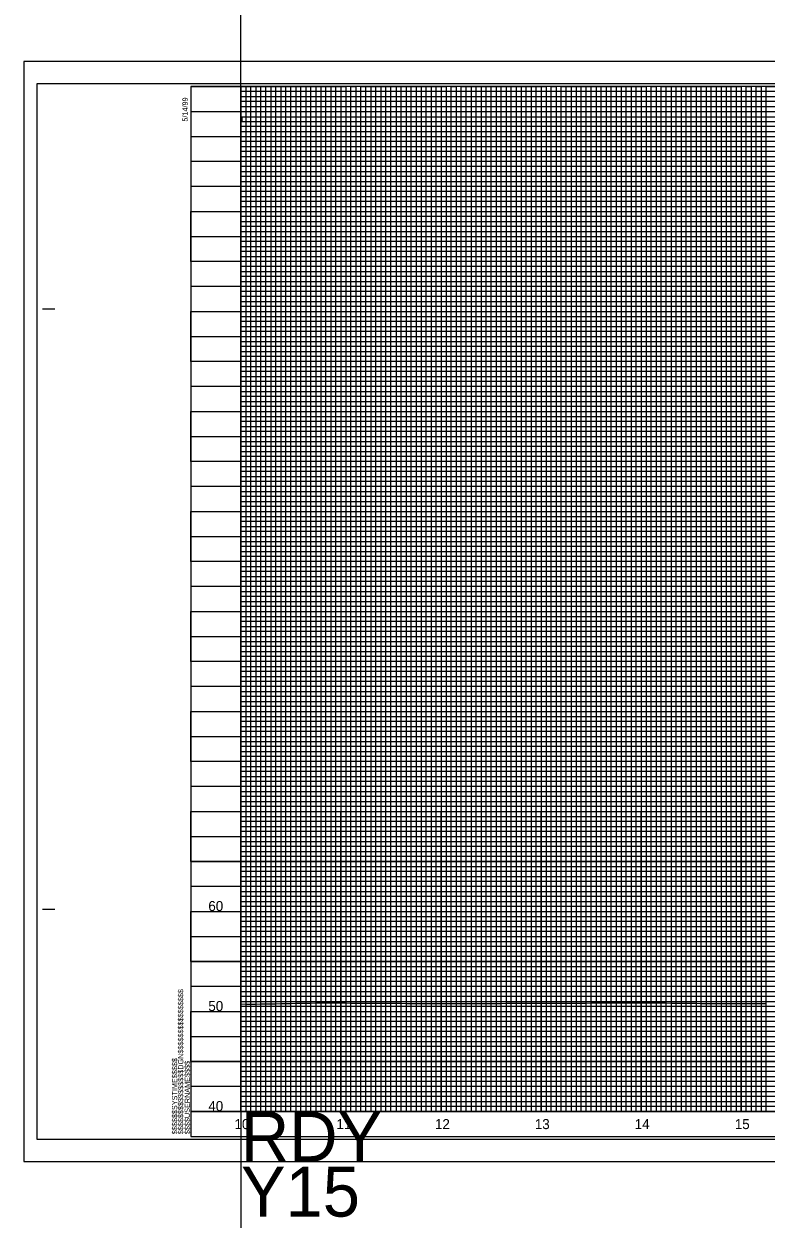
# Model space of a CAD drawing. Extents: x 2345490 to 2436403, y 465165 to 573888.
# Drawn here: x 2381550 to 2382292, y 523436 to 524631 of the extents above; entities that cross this region are included whole.
import ezdxf

# ---------------------------------------------------------------- set-up
doc = ezdxf.new("R2010")
doc.units = 0
for name, color, linetype in [('Old_Level_1', 7, 'Continuous'), ('Old_Level_18', 7, 'Continuous'), ('Old_Level_40', 7, 'Continuous'), ('Old_Level_41', 7, 'Continuous'), ('Old_Level_42', 7, 'Continuous'), ('Old_Level_43', 7, 'Continuous'), ('Old_Level_50', 7, 'Continuous'), ('Old_Level_51', 7, 'Continuous'), ('Old_Level_52', 7, 'Continuous'), ('Old_Level_57', 7, 'Continuous'), ('Old_Level_63', 7, 'Continuous')]:
    doc.layers.add(name, color=color, linetype=linetype)

msp = doc.modelspace()

# ---------------------------------------------------------------- linework, layer by layer
at = {"layer": 'Old_Level_1'}
for points in [[(2381766.799, 523650.76525), (2381771.799, 523650.5205), (2381776.799, 523650.612), (2381781.799, 523650.7035), (2381786.799, 523650.795), (2381791.799, 523650.8865), (2381796.799, 523650.978), (2381801.799, 523651.0665), (2381806.799, 523651.15825), (2381811.799, 523651.24975), (2381816.799, 523651.34125), (2381821.799, 523651.433), (2381826.799, 523651.5245), (2381831.799, 523651.6135), (2381836.799, 523651.70525), (2381841.799, 523651.797), (2381846.799, 523651.8885), (2381851.799, 523651.882), (2381856.799, 523651.84925), (2381861.799, 523651.81675), (2381866.799, 523651.784), (2381871.799, 523651.7515), (2381876.799, 523651.71875), (2381881.799, 523651.6925), (2381886.799, 523651.6605), (2381891.799, 523651.62825), (2381896.799, 523651.59625), (2381901.799, 523651.56425), (2381906.799, 523651.532), (2381911.799, 523651.51125), (2381916.799, 523651.47975), (2381921.799, 523651.44825), (2381926.799, 523651.417), (2381931.799, 523651.40325), (2381936.799, 523651.3975), (2381941.799, 523651.39175), (2381946.799, 523651.38575), (2381951.799, 523651.38), (2381956.799, 523651.37425), (2381961.799, 523651.371), (2381966.799, 523651.3645), (2381971.799, 523651.358), (2381976.799, 523651.3515), (2381981.799, 523651.34575), (2381986.799, 523651.3405), (2381991.799, 523651.336), (2381996.799, 523651.33125), (2382001.799, 523651.32625), (2382006.799, 523651.3215), (2382011.799, 523651.328), (2382016.799, 523651.3485), (2382021.799, 523651.369), (2382026.799, 523651.3895), (2382031.799, 523651.40975), (2382036.799, 523651.43025), (2382041.799, 523651.45075), (2382046.799, 523651.47125), (2382051.799, 523651.4915), (2382056.799, 523651.512), (2382061.799, 523651.5325), (2382066.799, 523651.553), (2382071.799, 523651.5735), (2382076.799, 523651.594), (2382081.799, 523651.61425), (2382086.799, 523651.63475), (2382091.799, 523651.6555), (2382096.799, 523651.677), (2382101.799, 523651.6985), (2382106.799, 523651.71925), (2382111.799, 523651.74025), (2382116.799, 523651.761), (2382121.799, 523651.78175), (2382126.799, 523651.8025), (2382131.799, 523651.82325), (2382136.799, 523651.84175), (2382141.799, 523651.86225), (2382146.799, 523651.88275), (2382151.799, 523651.90325), (2382156.799, 523651.92375), (2382161.799, 523651.9445), (2382166.799, 523651.965), (2382171.799, 523651.94075), (2382176.799, 523651.90025), (2382181.799, 523651.8575), (2382186.799, 523651.81275), (2382191.799, 523651.766), (2382196.799, 523651.717), (2382201.799, 523651.66625), (2382206.799, 523651.61325), (2382211.799, 523651.5585), (2382216.799, 523651.5015), (2382221.799, 523651.4425), (2382226.799, 523651.396), (2382231.799, 523651.35075), (2382236.799, 523651.28625), (2382241.799, 523651.21925), (2382246.799, 523651.187), (2382251.799, 523651.229), (2382256.799, 523651.25125), (2382261.799, 523651.271), (2382266.799, 523651.28825)], [(2382266.799, 523651.28825), (2382271.799, 523651.303), (2382276.799, 523651.315), (2382281.799, 523651.32475), (2382286.799, 523651.332), (2382291.799, 523651.3365)]]:
    msp.add_lwpolyline(points, dxfattribs=at)
at = {"layer": 'Old_Level_18'}
msp.add_line((2381716.79875, 523518.168), (2381716.79875, 523518.168), dxfattribs=at)
msp.add_line((2381716.79875, 523518.168), (2381716.79875, 523518.168), dxfattribs=at)
msp.add_lwpolyline([(2383216.79875, 524568.168), (2381716.79875, 524568.168), (2381716.79875, 523518.168), (2383216.79875, 523518.168)], close=True, dxfattribs=at)
at = {"layer": 'Old_Level_40'}
msp.add_line((2381716.79875, 523518.168), (2381716.79875, 523518.168), dxfattribs=at)
msp.add_line((2381716.79875, 523518.168), (2381716.79875, 523518.168), dxfattribs=at)
msp.add_line((2381716.79875, 523518.168), (2381716.79875, 523518.168), dxfattribs=at)
msp.add_line((2381716.79875, 523518.168), (2381716.79875, 523518.168), dxfattribs=at)
at = {"layer": 'Old_Level_41'}
for p, q in [((2381568.29875, 524345.668), (2381580.79875, 524345.668)), ((2381568.29875, 523745.668), (2381580.79875, 523745.668)), ((2383216.79875, 523543.168), (2381716.79875, 523543.168))]:
    msp.add_line(p, q, dxfattribs=at)
for points in [[(2381716.79875, 524568.168), (2381766.79875, 524568.168), (2381766.79875, 523543.168), (2381816.79875, 523543.168), (2381816.79875, 524568.168), (2381866.79875, 524568.168), (2381866.79875, 523543.168), (2381916.79875, 523543.168), (2381916.79875, 524568.168), (2381966.79875, 524568.168), (2381966.79875, 523543.168), (2382016.79875, 523543.168), (2382016.79875, 524568.168), (2382066.79875, 524568.168), (2382066.79875, 523543.168), (2382116.79875, 523543.168), (2382116.79875, 524568.168), (2382166.79875, 524568.168), (2382166.79875, 523543.168), (2382216.79875, 523543.168), (2382216.79875, 524568.168), (2382266.79875, 524568.168), (2382266.79875, 523543.168), (2382316.79875, 523543.168)], [(2381791.79875, 523543.168), (2381791.79875, 524568.168), (2381841.79875, 524568.168), (2381841.79875, 523543.168), (2381891.79875, 523543.168), (2381891.79875, 524568.168), (2381941.79875, 524568.168), (2381941.79875, 523543.168), (2381991.79875, 523543.168), (2381991.79875, 524568.168), (2382041.79875, 524568.168), (2382041.79875, 523543.168), (2382091.79875, 523543.168), (2382091.79875, 524568.168), (2382141.79875, 524568.168), (2382141.79875, 523543.168), (2382191.79875, 523543.168), (2382191.79875, 524568.168), (2382241.79875, 524568.168), (2382241.79875, 523543.168), (2382291.79875, 523543.168), (2382291.79875, 524568.168), (2382341.79875, 524568.168)], [(2381716.79875, 524518.168), (2383016.74875, 524518.168)], [(2383016.74875, 524468.168), (2381716.79875, 524468.168), (2381716.79875, 524418.118), (2383216.79875, 524418.118)], [(2383216.79875, 524393.168), (2381716.79875, 524393.168), (2381716.79875, 524443.168), (2383016.74875, 524443.168)], [(2383216.79875, 524368.168), (2381716.79875, 524368.168), (2381716.79875, 524318.168), (2383216.79875, 524318.168)], [(2383216.79875, 524293.168), (2381716.79875, 524293.168), (2381716.79875, 524343.168), (2383216.79875, 524343.168)], [(2383216.79875, 524268.168), (2381716.79875, 524268.168), (2381716.79875, 524218.168), (2383216.79875, 524218.168)], [(2383216.79875, 524168.168), (2381716.79875, 524168.168), (2381716.79875, 524118.168), (2383216.79875, 524118.168)], [(2383216.79875, 524068.168), (2381716.79875, 524068.168), (2381716.79875, 524018.168), (2383216.79875, 524018.168)], [(2383216.79875, 523968.168), (2381716.79875, 523968.168), (2381716.79875, 523918.168), (2383216.79875, 523918.168)], [(2383216.79875, 523893.168), (2381716.79875, 523893.168), (2381716.79875, 523943.168), (2383216.79875, 523943.168)], [(2383216.79875, 523868.168), (2381716.79875, 523868.168), (2381716.79875, 523818.168), (2383216.79875, 523818.168)], [(2383216.79875, 523793.168), (2381716.79875, 523793.168), (2381716.79875, 523843.168), (2383216.79875, 523843.168)], [(2383216.79875, 523768.168), (2381716.79875, 523768.168), (2381716.79875, 523718.168), (2383216.79875, 523718.168)], [(2383216.79875, 523668.168), (2381716.79875, 523668.168), (2381716.79875, 523618.168), (2383216.79875, 523618.168)], [(2383216.79875, 523593.168), (2381716.79875, 523593.168), (2381716.79875, 523643.168), (2383216.79875, 523643.168)], [(2383216.79875, 523568.168), (2381716.79875, 523568.168)], [(2381754.29875, 523518.168), (2381754.29875, 523518.168)]]:
    msp.add_lwpolyline(points, dxfattribs=at)
at = {"layer": 'Old_Level_42'}
for points in [[(2383016.74875, 524493.168), (2381716.89875, 524493.168), (2381716.89875, 524543.118), (2383016.74875, 524543.118)], [(2383216.79875, 524193.168), (2381716.79875, 524193.168), (2381716.79875, 524243.168), (2383216.79875, 524243.168)], [(2383216.79875, 524093.168), (2381716.79875, 524093.168), (2381716.79875, 524143.168), (2383216.79875, 524143.168)], [(2383216.79875, 523993.168), (2381716.79875, 523993.168), (2381716.79875, 524043.168), (2383216.79875, 524043.168)], [(2383216.79875, 523693.168), (2381716.79875, 523693.168), (2381716.79875, 523743.168), (2383216.79875, 523743.168)]]:
    msp.add_lwpolyline(points, dxfattribs=at)
at = {"layer": 'Old_Level_43'}
for p, q in [((2383166.79875, 524388.168), (2381766.79875, 524388.168)), ((2381766.79875, 524388.168), (2381766.79875, 524383.168)), ((2381766.79875, 524383.168), (2383166.79875, 524383.168)), ((2383166.79875, 524363.168), (2381766.79875, 524363.168))]:
    msp.add_line(p, q, dxfattribs=at)
for points in [[(2381771.79875, 524568.168), (2381776.79875, 524568.168), (2381781.79875, 524568.168), (2381786.79875, 524568.168), (2381796.79875, 524568.168), (2381763.74875, 524568.168), (2381768.74875, 524568.168), (2381726.79875, 524568.168), (2381731.79875, 524568.168), (2381736.79875, 524568.168), (2381746.79875, 524568.168), (2381751.79875, 524568.168), (2381756.79875, 524568.168), (2381761.79875, 524568.168), (2381771.79875, 524568.168), (2381771.79875, 523543.168), (2381776.79875, 523543.168), (2381776.79875, 524568.168), (2381781.79875, 524568.168), (2381781.79875, 523543.168), (2381786.79875, 523543.168), (2381786.79875, 524568.168), (2381796.79875, 524568.168), (2381796.79875, 523543.168), (2381801.79875, 523543.168), (2381801.79875, 524568.168), (2381806.79875, 524568.168), (2381806.79875, 523543.168), (2381811.79875, 523543.168), (2381811.79875, 524568.168), (2381821.79875, 524568.168), (2381821.79875, 523543.168), (2381826.79875, 523543.168), (2381826.79875, 524568.168), (2381831.79875, 524568.168), (2381831.79875, 523543.168), (2381836.79875, 523543.168), (2381836.79875, 524568.168), (2381846.79875, 524568.168), (2381846.79875, 523543.168), (2381851.79875, 523543.168), (2381851.79875, 524568.168), (2381856.79875, 524568.168), (2381856.79875, 523543.168), (2381861.79875, 523543.168), (2381861.79875, 524568.168), (2381871.79875, 524568.168), (2381871.79875, 523543.168), (2381876.79875, 523543.168), (2381876.79875, 524568.168), (2381881.79875, 524568.168), (2381881.79875, 523543.168), (2381886.79875, 523543.168), (2381886.79875, 524568.168), (2381896.79875, 524568.168), (2381896.79875, 523543.168), (2381901.79875, 523543.168), (2381901.79875, 524568.168), (2381906.79875, 524568.168), (2381906.79875, 523543.168), (2381911.79875, 523543.168), (2381911.79875, 524568.168), (2381921.79875, 524568.168), (2381921.79875, 523543.168), (2381926.79875, 523543.168), (2381926.79875, 524568.168), (2381931.79875, 524568.168), (2381931.79875, 523543.168)], [(2381931.79875, 523543.168), (2381936.79875, 523543.168), (2381936.79875, 524568.168), (2381946.79875, 524568.168), (2381946.79875, 523543.168), (2381951.79875, 523543.168), (2381951.79875, 524568.168), (2381956.79875, 524568.168), (2381956.79875, 523543.168), (2381961.79875, 523543.168), (2381961.79875, 524568.168), (2381971.79875, 524568.168), (2381971.79875, 523543.168), (2381976.79875, 523543.168), (2381976.79875, 524568.168), (2381976.79875, 524568.168), (2381981.79875, 524568.168), (2381981.79875, 523543.168), (2381986.79875, 523543.168), (2381986.79875, 524568.168), (2381996.79875, 524568.168), (2381996.79875, 523543.168), (2382001.79875, 523543.168), (2382001.79875, 524568.168), (2382006.79875, 524568.168), (2382006.79875, 523543.168), (2382011.79875, 523543.168), (2382011.79875, 524568.168), (2382021.79875, 524568.168), (2382021.79875, 523543.168), (2382026.79875, 523543.168), (2382026.79875, 524568.168), (2382031.79875, 524568.168), (2382031.79875, 523543.168), (2382036.79875, 523543.168), (2382036.79875, 524568.168), (2382046.79875, 524568.168), (2382046.79875, 523543.168), (2382051.79875, 523543.168), (2382051.79875, 524568.168), (2382056.79875, 524568.168), (2382056.79875, 523543.168), (2382061.79875, 523543.168), (2382061.79875, 524568.168), (2382071.79875, 524568.168), (2382071.79875, 523543.168), (2382076.79875, 523543.168), (2382076.79875, 524568.168), (2382081.79875, 524568.168), (2382081.79875, 523543.168), (2382086.79875, 523543.168), (2382086.79875, 524568.168), (2382096.79875, 524568.168), (2382096.79875, 523543.168), (2382111.79875, 523543.168), (2382111.79875, 524568.168), (2382121.79875, 524568.168), (2382121.79875, 523543.168), (2382126.79875, 523543.168), (2382126.79875, 524568.168), (2382131.79875, 524568.168), (2382131.79875, 523543.168), (2382136.79875, 523543.168), (2382136.79875, 524568.168), (2382146.79875, 524568.168), (2382146.79875, 523543.168), (2382151.79875, 523543.168), (2382151.79875, 524568.168), (2382156.79875, 524568.168), (2382156.79875, 523543.168), (2382161.79875, 523543.168), (2382161.79875, 524568.168), (2382171.79875, 524568.168), (2382171.79875, 523543.168), (2382176.79875, 523543.168), (2382176.79875, 524568.168), (2382181.79875, 524568.168), (2382181.79875, 523543.168), (2382186.79875, 523543.168), (2382186.79875, 524568.168), (2382196.79875, 524568.168), (2382196.79875, 523543.168), (2382201.79875, 523543.168), (2382201.79875, 524568.168), (2382206.79875, 524568.168), (2382206.79875, 523543.168), (2382211.79875, 523543.168), (2382211.79875, 524568.168), (2382221.79875, 524568.168), (2382221.79875, 523543.168), (2382226.79875, 523543.168), (2382226.79875, 524568.168), (2382231.79875, 524568.168), (2382231.79875, 523543.168), (2382236.79875, 523543.168), (2382236.79875, 524568.168), (2382246.79875, 524568.168), (2382246.79875, 523543.168)], [(2382101.79875, 524568.168), (2382101.79875, 523543.168), (2382106.79875, 523543.168), (2382106.79875, 524568.168)], [(2382101.79875, 524567.568), (2382101.79875, 523543.168), (2382106.79875, 523543.168), (2382106.79875, 524567.568)], [(2382251.79875, 524568.168), (2382251.79875, 523543.168), (2382256.79875, 523543.168), (2382256.79875, 524568.168), (2382261.79875, 524568.168), (2382261.79875, 523543.168), (2382271.79875, 523543.168), (2382271.79875, 524568.168), (2382276.79875, 524568.168), (2382276.79875, 523543.168), (2382281.79875, 523543.168), (2382281.79875, 524568.168), (2382286.79875, 524568.168), (2382286.79875, 523543.168)], [(2383016.74875, 524563.168), (2381766.79875, 524563.168), (2381766.79875, 524558.168), (2383016.74875, 524558.168)], [(2383016.74875, 524553.168), (2381766.79875, 524553.168), (2381766.79875, 524548.168), (2383016.74875, 524548.168)], [(2383016.74875, 524537.418), (2381767.79875, 524537.418), (2381767.79875, 524533.168), (2383016.74875, 524533.168)], [(2383016.74875, 524528.168), (2381766.79875, 524528.168), (2381766.79875, 524523.168), (2383016.74875, 524523.168)], [(2383016.74875, 524513.168), (2381766.79875, 524513.168), (2381766.79875, 524508.168), (2383016.74875, 524508.168)], [(2383016.74875, 524503.168), (2381766.79875, 524503.168), (2381766.79875, 524498.168), (2383016.74875, 524498.168)], [(2383016.74875, 524488.168), (2381766.79875, 524488.168), (2381766.79875, 524483.168), (2383016.74875, 524483.168)], [(2383016.74875, 524478.168), (2381766.79875, 524478.168), (2381766.79875, 524473.168), (2383016.74875, 524473.168)], [(2383016.74875, 524463.168), (2381766.79875, 524463.168), (2381766.79875, 524458.168), (2383016.74875, 524458.168)], [(2383016.74875, 524453.168), (2381766.79875, 524453.168), (2381766.79875, 524448.168), (2383016.74875, 524448.168)], [(2383016.74875, 524438.168), (2381766.79875, 524438.168), (2381766.79875, 524433.168), (2383016.74875, 524433.168)], [(2383166.79875, 524428.168), (2381766.79875, 524428.168), (2381766.79875, 524428.168), (2381766.79875, 524408.168), (2383166.79875, 524408.168)], [(2381766.79875, 524423.168), (2383166.79875, 524423.168)], [(2383166.79875, 524413.168), (2381766.79875, 524413.168)], [(2383166.79875, 524403.168), (2381766.79875, 524403.168), (2381766.79875, 524398.168), (2383166.79875, 524398.168)], [(2383166.79875, 524378.168), (2381766.79875, 524378.168), (2381766.79875, 524373.168), (2383166.79875, 524373.168)], [(2383166.79875, 524358.168), (2381766.79875, 524358.168), (2381766.79875, 524353.168), (2383166.79875, 524353.168)], [(2383166.79875, 524348.168), (2381766.79875, 524348.168)], [(2381766.79875, 524338.168), (2383166.79875, 524338.168)], [(2383166.79875, 524333.168), (2381766.79875, 524333.168), (2381766.79875, 524328.168), (2383166.79875, 524328.168)], [(2383166.79875, 524323.168), (2381766.79875, 524323.168), (2381766.79875, 524313.168), (2383166.79875, 524313.168)], [(2383166.79875, 524308.168), (2381766.79875, 524308.168), (2381766.79875, 524303.168), (2383166.79875, 524303.168)], [(2383166.79875, 524298.168), (2381766.79875, 524298.168), (2381766.79875, 524288.168), (2383166.79875, 524288.168)], [(2383166.79875, 524283.168), (2381766.79875, 524283.168), (2381766.79875, 524278.168), (2383166.79875, 524278.168)], [(2383166.79875, 524273.168), (2381766.79875, 524273.168), (2381766.79875, 524263.168), (2383166.79875, 524263.168)], [(2383166.79875, 524258.168), (2381766.79875, 524258.168), (2381766.79875, 524253.168), (2383166.79875, 524253.168)], [(2383166.79875, 524248.168), (2381766.79875, 524248.168), (2381766.79875, 524238.168), (2383166.79875, 524238.168)], [(2383166.79875, 524233.168), (2381766.79875, 524233.168), (2381766.79875, 524228.168), (2383166.79875, 524228.168)], [(2383166.79875, 524223.168), (2381766.79875, 524223.168), (2381766.79875, 524213.168), (2383166.79875, 524213.168)], [(2383166.79875, 524208.168), (2381766.79875, 524208.168), (2381766.79875, 524203.168), (2383166.79875, 524203.168)], [(2383166.79875, 524198.168), (2381766.79875, 524198.168), (2381766.79875, 524188.168), (2383166.79875, 524188.168)], [(2383166.79875, 524183.168), (2381766.79875, 524183.168), (2381766.79875, 524178.168), (2383166.79875, 524178.168)], [(2383166.79875, 524173.168), (2381766.79875, 524173.168), (2381766.79875, 524163.168), (2383166.79875, 524163.168)], [(2383166.79875, 524158.168), (2381766.79875, 524158.168), (2381766.79875, 524153.168), (2383166.79875, 524153.168)], [(2383166.79875, 524148.168), (2381766.79875, 524148.168), (2381766.79875, 524138.168), (2383166.79875, 524138.168)], [(2383166.79875, 524133.168), (2381766.79875, 524133.168), (2381766.79875, 524128.168), (2383166.79875, 524128.168)], [(2383166.79875, 524123.168), (2381766.79875, 524123.168), (2381766.79875, 524113.168), (2383166.79875, 524113.168)], [(2383166.79875, 524108.168), (2381766.79875, 524108.168), (2381766.79875, 524103.168), (2383166.79875, 524103.168)], [(2383166.79875, 524098.168), (2381766.79875, 524098.168), (2381766.79875, 524088.168), (2383166.79875, 524088.168)], [(2383166.79875, 524083.168), (2381766.79875, 524083.168), (2381766.79875, 524078.168), (2383166.79875, 524078.168)], [(2383166.79875, 524073.168), (2381766.79875, 524073.168), (2381766.79875, 524063.168), (2383166.79875, 524063.168)], [(2383166.79875, 524058.168), (2381766.79875, 524058.168), (2381766.79875, 524053.168), (2383166.79875, 524053.168)], [(2383166.79875, 524048.168), (2381766.79875, 524048.168)], [(2381766.79875, 524038.168), (2383166.79875, 524038.168)], [(2383166.79875, 524033.168), (2381766.79875, 524033.168), (2381766.79875, 524028.168), (2383166.79875, 524028.168)], [(2383166.79875, 524023.168), (2381766.79875, 524023.168), (2381766.79875, 524013.168), (2383166.79875, 524013.168)], [(2383166.79875, 524008.168), (2381766.79875, 524008.168), (2381766.79875, 524003.168), (2383166.79875, 524003.168)], [(2383166.79875, 523998.168), (2381766.79875, 523998.168), (2381766.79875, 523988.168), (2383166.79875, 523988.168)], [(2383166.79875, 523983.168), (2381766.79875, 523983.168), (2381766.79875, 523978.168), (2383166.79875, 523978.168)], [(2383166.79875, 523973.168), (2381766.79875, 523973.168), (2381766.79875, 523963.168), (2383166.79875, 523963.168)], [(2383166.79875, 523958.168), (2381766.79875, 523958.168), (2381766.79875, 523953.168), (2383166.79875, 523953.168)], [(2383166.79875, 523948.168), (2381766.79875, 523948.168), (2381766.79875, 523938.168), (2383166.79875, 523938.168)], [(2383166.79875, 523933.168), (2381766.79875, 523933.168), (2381766.79875, 523928.168), (2383166.79875, 523928.168)], [(2383166.79875, 523923.168), (2381766.79875, 523923.168), (2381766.79875, 523913.168), (2383166.79875, 523913.168)], [(2383166.79875, 523908.168), (2381766.79875, 523908.168), (2381766.79875, 523903.168), (2383166.79875, 523903.168)], [(2383166.79875, 523898.168), (2381766.79875, 523898.168), (2381766.79875, 523888.168), (2383166.79875, 523888.168)], [(2383166.79875, 523883.168), (2381766.79875, 523883.168), (2381766.79875, 523878.168), (2383166.79875, 523878.168)], [(2383166.79875, 523873.168), (2381766.79875, 523873.168), (2381766.79875, 523863.168), (2383166.79875, 523863.168)], [(2383166.79875, 523858.168), (2381766.79875, 523858.168), (2381766.79875, 523853.168), (2383166.79875, 523853.168)], [(2383166.79875, 523848.168), (2381766.79875, 523848.168), (2381766.79875, 523838.168), (2383166.79875, 523838.168)], [(2383166.79875, 523833.168), (2381766.79875, 523833.168), (2381766.79875, 523828.168), (2383166.79875, 523828.168)], [(2383166.79875, 523823.168), (2381766.79875, 523823.168), (2381766.79875, 523813.168), (2383166.79875, 523813.168)], [(2383166.79875, 523808.168), (2381766.79875, 523808.168), (2381766.79875, 523803.168), (2383166.79875, 523803.168)], [(2383166.79875, 523798.168), (2381766.79875, 523798.168), (2381766.79875, 523788.168), (2383166.79875, 523788.168)], [(2383166.79875, 523783.168), (2381766.79875, 523783.168), (2381766.79875, 523778.168), (2383166.79875, 523778.168)], [(2383166.79875, 523773.168), (2381766.79875, 523773.168), (2381766.79875, 523763.168), (2383166.79875, 523763.168)], [(2383166.79875, 523758.168), (2381766.79875, 523758.168), (2381766.79875, 523753.168), (2383166.79875, 523753.168)], [(2383166.79875, 523748.168), (2381766.79875, 523748.168)], [(2381766.79875, 523738.168), (2383166.79875, 523738.168)], [(2383166.79875, 523733.168), (2381766.79875, 523733.168), (2381766.79875, 523728.168), (2383166.79875, 523728.168)], [(2383166.79875, 523723.168), (2381766.79875, 523723.168)], [(2381766.79875, 523713.168), (2383166.79875, 523713.168)], [(2383166.79875, 523708.168), (2381766.79875, 523708.168), (2381766.79875, 523703.168), (2383166.79875, 523703.168)], [(2383166.79875, 523698.168), (2381766.79875, 523698.168), (2381766.79875, 523688.168), (2383166.79875, 523688.168)], [(2383166.79875, 523683.168), (2381766.79875, 523683.168), (2381766.79875, 523678.168), (2383166.79875, 523678.168)], [(2383166.79875, 523673.168), (2381766.79875, 523673.168), (2381766.79875, 523663.168), (2383166.79875, 523663.168)], [(2383166.79875, 523658.168), (2381766.79875, 523658.168), (2381766.79875, 523653.168), (2383166.79875, 523653.168)], [(2383166.79875, 523648.168), (2381766.79875, 523648.168), (2381766.79875, 523638.168), (2383166.79875, 523638.168)], [(2383166.79875, 523633.168), (2381766.79875, 523633.168), (2381766.79875, 523628.168), (2383166.79875, 523628.168)], [(2383166.79875, 523623.168), (2381766.79875, 523623.168), (2381766.79875, 523613.168), (2383166.79875, 523613.168)], [(2383166.79875, 523608.168), (2381766.79875, 523608.168), (2381766.79875, 523603.168), (2383166.79875, 523603.168)], [(2383166.79875, 523598.168), (2381766.79875, 523598.168), (2381766.79875, 523588.168), (2383166.79875, 523588.168)], [(2383166.79875, 523583.168), (2381766.79875, 523583.168), (2381766.79875, 523578.168), (2383166.79875, 523578.168)], [(2383166.79875, 523573.168), (2381766.79875, 523573.168), (2381766.79875, 523563.168), (2383166.79875, 523563.168)], [(2383166.79875, 523558.168), (2381766.79875, 523558.168), (2381766.79875, 523553.168), (2383166.79875, 523553.168)], [(2383166.79875, 523548.168), (2381766.79875, 523548.168)]]:
    msp.add_lwpolyline(points, dxfattribs=at)
at = {"layer": 'Old_Level_50'}
msp.add_line((2381549.79875, 523493.168), (2381549.79875, 523493.168), dxfattribs=at)
msp.add_lwpolyline([(2383229.29875, 524570.718), (2381562.79875, 524570.718), (2381562.79875, 523515.618), (2383229.29875, 523515.618)], close=True, dxfattribs=at)
at = {"layer": 'Old_Level_51'}
msp.add_lwpolyline([(2383233.79875, 524593.168), (2381549.79875, 524593.168), (2381549.79875, 523493.168), (2383233.79875, 523493.168)], close=True, dxfattribs=at)
at = {"layer": 'Old_Level_52'}
msp.add_line((2381562.79875, 523515.618), (2381562.79875, 523515.618), dxfattribs=at)
at = {"layer": 'Old_Level_57'}
for p, q in [((2381716.79925, 523843.16825), (2384066.79875, 523843.16825)), ((2381766.79875, 523543.16825), (2381766.79875, 523843.16825)), ((2381866.79875, 523543.16825), (2381866.79875, 523843.16825)), ((2381966.79875, 523543.16825), (2381966.79875, 523843.16825)), ((2382066.79875, 523543.16825), (2382066.79875, 523843.16825)), ((2382166.79875, 523543.16825), (2382166.79875, 523843.16825)), ((2382166.79875, 523543.26825), (2382166.79875, 523843.16825)), ((2382266.79875, 523543.16825), (2382266.79875, 523843.16825)), ((2382266.79875, 523543.26825), (2382266.79875, 523843.16825)), ((2381716.79925, 523793.16825), (2384066.79875, 523793.16825)), ((2381716.79925, 523743.16825), (2384066.79875, 523743.16825)), ((2381716.79925, 523693.16825), (2384066.79875, 523693.16825)), ((2381716.79925, 523643.16825), (2384066.79875, 523643.16825)), ((2381716.799, 523593.16825), (2384066.79875, 523593.16825)), ((2381716.79925, 523543.16825), (2384066.79875, 523543.16825))]:
    msp.add_line(p, q, dxfattribs=at)
at = {"layer": 'Old_Level_63'}
for q in [(2381766.79875, 526043.168), (2383942.32375, 523543.168), (2381766.79875, 521043.168)]:
    msp.add_line((2381766.79875, 523543.168), q, dxfattribs=at)

# ---------------------------------------------------------------- texts
at = {"layer": 'Old_Level_1'}
for s, p in [('60', (2381734.1855, 523743.668)), ('50', (2381734.1855, 523643.668)), ('40', (2381734.1855, 523543.668)), ('10', (2381760.3825, 523525.668)), ('11', (2381862.222, 523525.668)), ('12', (2381960.77025, 523525.668)), ('13', (2382060.605, 523525.668)), ('14', (2382160.4475, 523525.668)), ('15', (2382260.54, 523525.668))]:
    msp.add_text(s, height=10.000001, dxfattribs=at).set_placement(p)
at = {"layer": 'Old_Level_41'}
for s, p in [('5/14/99', (2381713.54875, 524532.968)), ('$$$$$$$$$$$$$$$$DGN$$$$$$$$$$$$$$$$', (2381709.14875, 523520.5305)), ('$$$$$$SYSTIME$$$$$', (2381703.09875, 523520.5305)), ('$$$$USERNAME$$$$', (2381715.72375, 523520.543))]:
    msp.add_text(s, height=5.25, rotation=90, dxfattribs=at).set_placement(p)
at = {"layer": 'Old_Level_63'}
for s, p in [('RDY', (2381766.79875, 523493.168)), ('Y15', (2381766.79875, 523438.16825))]:
    msp.add_text(s, height=50, dxfattribs=at).set_placement(p)

doc.saveas('drawing.dxf')
